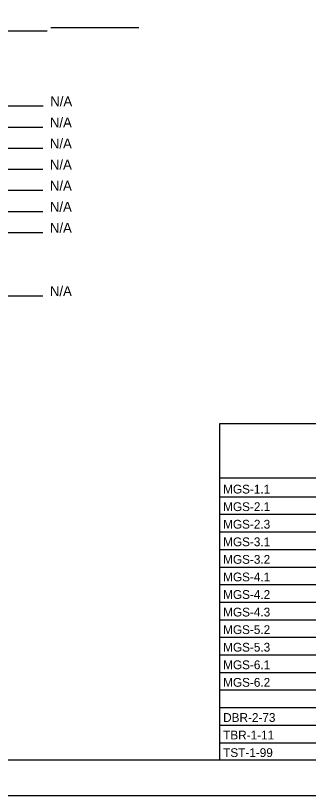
# Model space of a CAD drawing. Extents: x 0 to 34, y 0 to 22.
# Drawn here: x 7.25 to 11.41, y 0 to 11.1 of the extents above; entities that cross this region are included whole.
import ezdxf

# ---------------------------------------------------------------- set-up
doc = ezdxf.new("R2010")
doc.units = 0
for name, color, linetype in [('Default', 7, 'Continuous'), ('SH_Border', 7, 'Continuous'), ('SH_Cut_Line', 7, 'Continuous'), ('SH_Data', 7, 'Continuous'), ('SH_Text', 7, 'Continuous')]:
    doc.layers.add(name, color=color, linetype=linetype)

msp = doc.modelspace()

# ---------------------------------------------------------------- linework, layer by layer
at = {"layer": 'SH_Border'}
msp.add_lwpolyline([(1.5, 21.5), (33.5, 21.5), (33.5, 0.5), (1.5, 0.5)], close=True, dxfattribs=at)
at = {"layer": 'SH_Cut_Line'}
msp.add_lwpolyline([(0, 0), (34, 0), (34, 22), (0, 22)], close=True, dxfattribs=at)
at = {"layer": 'SH_Data'}
for p, q in [((7.7, 10.877), (3.347, 10.877)), ((9, 10.922), (7.75, 10.922)), ((7.642, 9.806), (3.871, 9.806)), ((7.637, 9.506), (4.189, 9.506)), ((7.637, 9.206), (4.872, 9.206)), ((7.637, 8.906), (4.604, 8.906)), ((7.637, 8.606), (4.189, 8.606)), ((7.637, 8.306), (3.346, 8.306)), ((7.637, 8.006), (3.242, 8.006)), ((7.637, 7.106), (3.267, 7.106)), ((10.15, 5.292), (23.6, 5.292)), ((10.15, 0.5), (10.15, 5.292)), ((10.15, 4.521), (23.6, 4.521)), ((10.15, 4.25), (23.6, 4.25)), ((10.15, 4), (23.6, 4)), ((10.15, 3.75), (23.6, 3.75)), ((10.15, 3.5), (23.6, 3.5)), ((10.15, 3.25), (23.6, 3.25)), ((10.15, 3), (23.6, 3)), ((10.15, 2.75), (23.6, 2.75)), ((10.15, 2.5), (23.6, 2.5)), ((10.15, 2.25), (23.6, 2.25)), ((10.15, 2), (23.6, 2)), ((10.15, 1.75), (23.6, 1.75)), ((10.15, 1.5), (23.6, 1.5)), ((10.15, 1.25), (23.6, 1.25)), ((10.15, 1), (23.6, 1)), ((10.15, 0.75), (23.6, 0.75))]:
    msp.add_line(p, q, dxfattribs=at)

# ---------------------------------------------------------------- texts
at = {"layer": 'Default'}
for s, p in [('MGS-1.1', (10.199, 4.296)), ('MGS-2.1', (10.199, 4.046)), ('MGS-2.3', (10.199, 3.796)), ('MGS-3.1', (10.199, 3.546)), ('MGS-3.2', (10.199, 3.296)), ('MGS-4.1', (10.199, 3.046)), ('MGS-4.2', (10.199, 2.796)), ('MGS-4.3', (10.199, 2.546)), ('MGS-5.2', (10.199, 2.296)), ('MGS-5.3', (10.199, 2.046)), ('MGS-6.1', (10.199, 1.796)), ('MGS-6.2', (10.199, 1.546)), ('DBR-2-73', (10.199, 1.046)), ('TBR-1-11', (10.199, 0.796)), ('TST-1-99', (10.199, 0.546))]:
    msp.add_text(s, height=0.125, dxfattribs=at).set_placement(p)
at = {"layer": 'SH_Text'}
for p in [(7.742, 9.806), (7.737, 9.506), (7.737, 9.206), (7.737, 8.906), (7.737, 8.606), (7.737, 8.306), (7.737, 8.006), (7.737, 7.106)]:
    msp.add_text('N/A', height=0.14, dxfattribs=at).set_placement(p)

doc.saveas('drawing.dxf')
